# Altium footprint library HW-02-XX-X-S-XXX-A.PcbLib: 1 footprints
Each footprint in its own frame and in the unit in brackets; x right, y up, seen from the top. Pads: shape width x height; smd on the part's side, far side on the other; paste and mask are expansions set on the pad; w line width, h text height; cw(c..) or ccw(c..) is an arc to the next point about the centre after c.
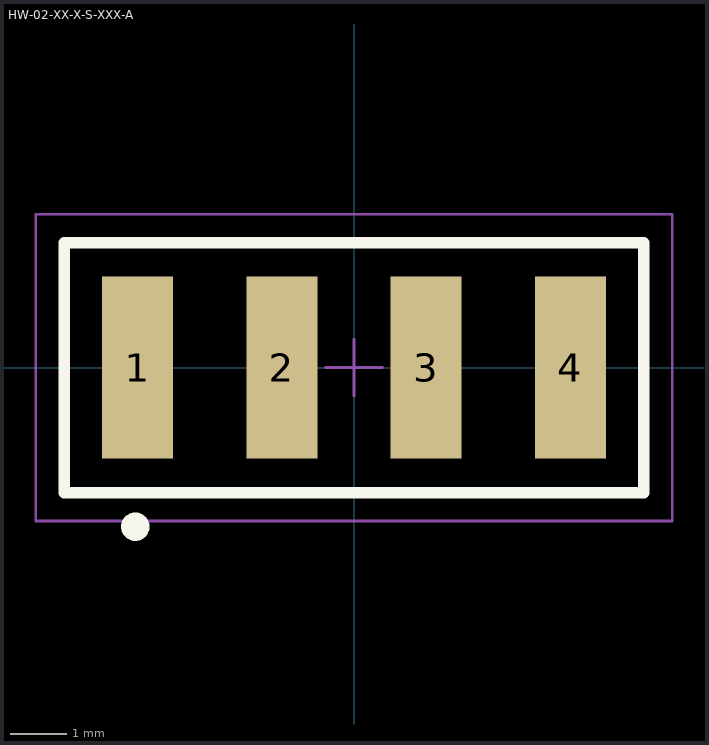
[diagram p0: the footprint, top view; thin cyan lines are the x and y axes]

## HW-02-XX-X-S-XXX-A [mm] "2.54mm pitch, 4 pin, board stacker; single row, SMT"
height 9.65
pads (4):
  rect 1.25x3.2 smd mask+0: 1(-3.81,0) 2(-1.27,0) 3(1.27,0) 4(3.81,0)
Top Overlay:
  circle w0.25: c-3.85,-2.8 r0.125
  lines w0.2: -5.1,-2.2 -5.1,2.2 5.1,2.2 5.1,-2.2 -5.1,-2.2
Mechanical 12:
  lines w0.001: -5.1,-2.2 -5.1,2.2 5.1,2.2 5.1,-2.2 -5.1,-2.2
Mechanical 13:
  lines w0.1: -5.1,-2.2 -5.1,2.2 5.1,2.2 5.1,-2.2 -5.1,-2.2
  text ".Designator" at 0.254,0.254 h1.52
Mechanical 15:
  lines w0.05: -0.5,0 0.5,0 ; 0,-0.5 0,0.5 ; -5.6,-2.7 5.6,-2.7 5.6,2.7 -5.6,2.7 -5.6,-2.7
